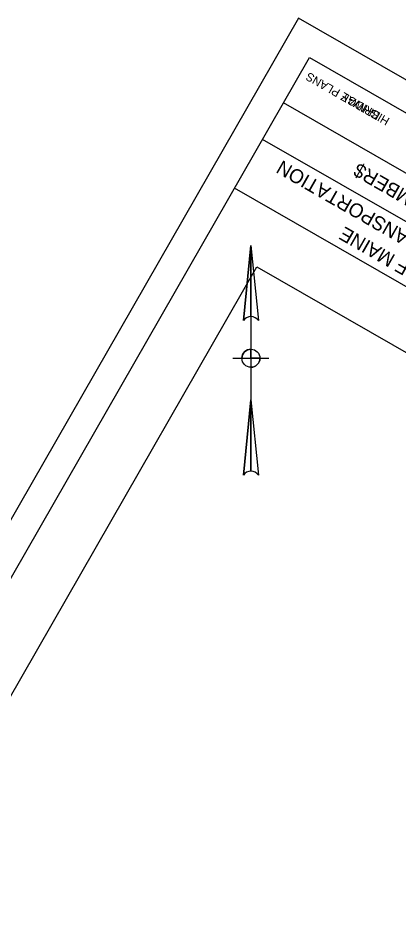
# Model space of a CAD drawing. Extents: x 1160447 to 1162032, y 616022 to 618272.
# Drawn here: x 1160776.4 to 1160902.9, y 616733 to 617033.1 of the extents above; entities that cross this region are included whole.
import ezdxf

# ---------------------------------------------------------------- set-up
doc = ezdxf.new("R2010")
doc.units = 0
for name, color, linetype in [('BORDER', 7, 'Continuous'), ('BRIDGE_TITLE', 7, 'Continuous'), ('H_V CONTROLS', 7, 'Continuous'), ('HIGHWAY_TITLE', 7, 'Continuous'), ('PLOT BOUNDARY', 7, 'Continuous'), ('Plot Boundary_1', 7, 'Continuous')]:
    doc.layers.add(name, color=color, linetype=linetype)

msp = doc.modelspace()

# ---------------------------------------------------------------- linework, layer by layer
at = {"layer": 'BORDER'}
for p, q in [((1160972.99, 616942.75), (1160864.56, 617004.94)), ((1160966.03, 616930.62), (1160857.6, 616992.82)), ((1161303.72, 616715.44), (1160848.31, 616976.65))]:
    msp.add_line(p, q, dxfattribs=at)
msp.add_lwpolyline([(1160475.14, 616326.08), (1160873.19, 617020.03), (1161328.59, 616758.81), (1160930.55, 616064.86)], close=True, dxfattribs=at)
at = {"layer": 'H_V CONTROLS'}
for p, q in [((1160851.27, 616932.65), (1160853.77, 616957.65)), ((1160853.77, 616957.65), (1160853.77, 616882.65)), ((1160853.77, 616957.65), (1160856.27, 616932.65)), ((1160847.77, 616920.15), (1160859.77, 616920.15)), ((1160851.27, 616881.31), (1160853.77, 616906.31)), ((1160853.77, 616906.31), (1160856.27, 616881.31))]:
    msp.add_line(p, q, dxfattribs=at)
for points in [[(1160853.77, 616933.99), (1160853.77, 616957.65), (1160851.27, 616932.65)], [(1160850.77, 616920.15), (1160853.77, 616920.15), (1160853.77, 616923.15)], [(1160856.77, 616920.15), (1160853.77, 616920.15), (1160853.77, 616917.15)], [(1160853.77, 616882.65), (1160853.77, 616906.31), (1160851.27, 616881.31)]]:
    msp.add_lwpolyline(points, dxfattribs=at)
msp.add_circle((1160853.77, 616920.15), 3, dxfattribs=at)
for centre, start, end in [((1160853.77, 616930.99), 33.5573, 146.4427), ((1160853.77, 616930.99), 90, 146.4427), ((1160853.77, 616920.15), 90, 180), ((1160853.77, 616920.15), 270, 0), ((1160853.77, 616879.65), 33.5573, 146.4427), ((1160853.77, 616879.65), 90, 146.4427)]:
    msp.add_arc(centre, 3, start, end, dxfattribs=at)
at = {"layer": 'PLOT BOUNDARY'}
msp.add_lwpolyline([(1160923.68, 616022.15), (1161346.6, 616759.47), (1160869.52, 617033.12), (1160446.59, 616295.81)], close=True, dxfattribs=at)
at = {"layer": 'Plot Boundary_1'}
msp.add_lwpolyline([(1160500.57, 616331.28), (1160855.78, 616950.54), (1161275.71, 616709.67), (1160920.5, 616090.41)], close=True, dxfattribs=at)

# ---------------------------------------------------------------- texts
at = {"layer": 'BORDER'}
for s, p in [('DEPARTMENT OF TRANSPORTATION', (1160961.66, 616930.12)), ('$PROJECTNUMBER$', (1160944.29, 616953.84)), ('STATE OF MAINE', (1160929.95, 616938.22))]:
    msp.add_text(s, height=4.6588, rotation=150.1613, dxfattribs=at).set_placement(p)
at = {"layer": 'BRIDGE_TITLE'}
msp.add_text('BRIDGE PLANS', height=2.795, rotation=150.1613, dxfattribs=at).set_placement((1160897.02, 617001.51))
at = {"layer": 'HIGHWAY_TITLE'}
msp.add_text('HIGHWAY PLANS', height=2.795, rotation=150.1613, dxfattribs=at).set_placement((1160900.09, 616999.75))

doc.saveas('drawing.dxf')
